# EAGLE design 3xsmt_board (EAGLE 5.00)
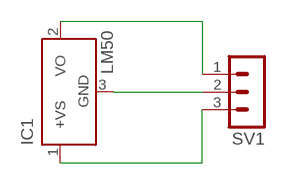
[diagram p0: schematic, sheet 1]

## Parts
IC1  LM50  [SOT23]
SV1  MA03-1  [MA03-1]

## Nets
P1: IC1.2(VO) SV1.1
P2: IC1.3(GND) SV1.2
P3: IC1.1(+VS) SV1.3

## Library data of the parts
IC1 = linear:LM50: SOT-23 Single-Supply Centigrade Temperature Sensor Vout = (10mV/°C x Temp °C) +5mmmV Source: http://cache.national.com/ds/LM/LM50.pdf
SV1 = con-lstb:MA03-1: PIN HEADER

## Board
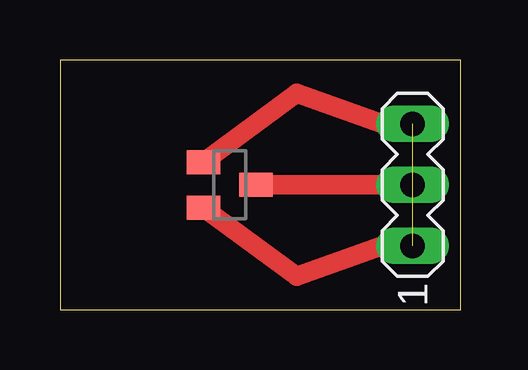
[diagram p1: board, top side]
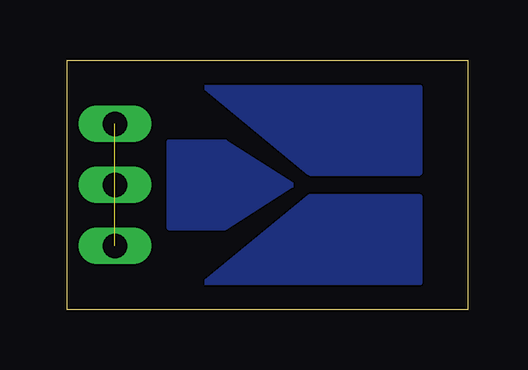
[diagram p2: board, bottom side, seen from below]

Size 16.69 x 10.4 mm. Coordinates in mm from the lower left corner, seen from the top.
Outline: 0,0 16.69,0 16.69,10.4 0,10.4 0,0
Copper layers (1*16): Top 0.035mm / dielectric 1.5mm / Bottom 0.035mm
Design rules "default": minimum track width 10mil, minimum drill 24mil, track to track 8mil, track to pad 8mil, pad to pad 8mil, via to via 8mil, smd to smd 8mil, copper to edge 40mil, drill to drill 8mil, minimum pad ring 10mil, minimum via ring 8mil, stop-mask expansion 4mil, vias tented up to drill 0mil, thermal gap 10mil

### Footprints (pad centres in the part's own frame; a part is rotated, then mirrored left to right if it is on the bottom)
SOT23 = smd 1 x 1.4: 1 -0.95,-1.1; 2 0.95,-1.1; 3 0,1.1
MA03-1 = drill 1.016 long: 1 -2.54,0; 2 0,0; 3 2.54,0

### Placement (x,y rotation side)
IC1  7.07,5.2 270 top
SV1  14.69,5.2 90 top

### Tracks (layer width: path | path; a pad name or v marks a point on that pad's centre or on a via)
N$1
  pour Bottom: 1.99,9.27 10.88,9.27 6.57,5.71 1.99,5.71
N$2
  pour Bottom: 10.12,6.98 7.33,5.2 10.12,3.42 12.41,3.42 12.41,6.98
N$3
  pour Bottom: 1.99,4.69 6.57,4.69 10.88,1.14 1.99,1.14
P1  (1 unrouted)
  Top 0.813: IC1.2 9.87,1.39 13.42,2.66 SV1.1
P2
  Top 0.813: IC1.3 SV1.2
P3
  Top 0.813: IC1.1 9.87,9.01 13.42,7.74 SV1.3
